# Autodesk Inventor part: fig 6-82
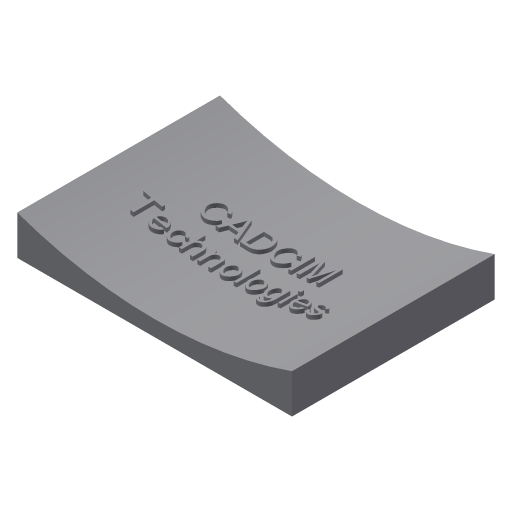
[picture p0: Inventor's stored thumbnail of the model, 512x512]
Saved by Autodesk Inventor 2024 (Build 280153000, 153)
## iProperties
Shininess: 64.0
Length Units: 11269
Angle Units: 11279
Time Units: 11290
Mass Units: 11283
Length Display Precision: 3
Angle Display Precision: 2
Compacted: True
Part Number: fig 6-82
Document SubType Name: Modeling
Created: 2002-12
Designer: deepak
Density: 1 g/cm^3
Material: Generic
Appearance: Default
Density: 0.0
Volumn: 0.0
Area: 0.0
PropertySet Name: Model Information
Control State: 0
Master: False
Checked Out: False
Author: deepak
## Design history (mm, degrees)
sketch "Sketch1"
  geometry: L1 (-39.922, 33.786)-(30.103, 33.786); L2 (30.103, 33.786)-(30.103, -17.894); L3 (30.103, -17.894)-(-39.922, -17.894); L4 (-39.922, -17.894)-(-39.922, 33.786)
  constraints: 8 end point, 2 parallel, 1 horizontal, 1 perpendicular
extrude "Extrusion1" new body sketch "Sketch1" distance "d0" = 10; taper "d1" = 0 deg
workplane "Work Plane1"
sketch "Sketch2"
  geometry: L1 (-37.656, 15.034)-(26.28, 15.034); L2 (26.28, 15.034)-(26.28, 10.168); L3 (26.28, 10.168)-(-37.656, 10.168); L4 (-37.656, 10.168)-(-37.656, 15.034)
  constraints: 2 other
sketch "Sketch3"
  geometry: L1 (70.026, 10)-(0, 10) reference; A1 r 105 centre (35.013, 108.99) between (0, 10) and (70.026, 10)
  constraints: 2 point on circle, 1 centre point
  dimensions: "d5" = 105 radius of A1
extrude "Extrusion2" cut sketch "Sketch3" extent not by distance; stored distance "d3" = 10; taper "d4" = 0 deg
emboss "Emboss4" sketch "Sketch2" dims "d14" = 1, "d15" = 0
body "Solid1"
other parameters: "d2" = 5
